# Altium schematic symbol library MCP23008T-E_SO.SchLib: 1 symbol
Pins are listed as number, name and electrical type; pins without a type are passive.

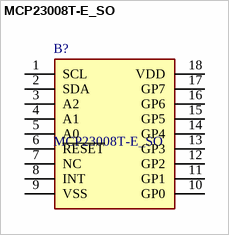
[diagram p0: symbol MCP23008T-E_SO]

## MCP23008T-E_SO
designator B?
Interface - I/O Expanders In/Out I2C int; Manufacturer_Name: Microchip; Manufacturer_Part_Number: MCP23008T-E/SO; Geometry.Height: 2.65mm
footprint SOIC127P1030X265-18N
pins: 1 SCL, 2 SDA, 3 A2, 4 A1, 5 A0, 6 ~{RESET}, 7 NC, 8 INT, 9 VSS, 10 GP0, 11 GP1, 12 GP2, 13 GP3, 14 GP4, 15 GP5, 16 GP6, 17 GP7, 18 VDD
